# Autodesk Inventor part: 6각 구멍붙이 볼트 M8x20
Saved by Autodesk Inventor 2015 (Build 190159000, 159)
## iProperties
Created: 2025-06
Part Number: 6각 구멍붙이 볼트 M8x20
Material: 일반
Document SubType Name: Modeling
Designer: User
Density: 1 g/cm^3
Appearance: 기본값
Author: User
Author: jhkim
Description: 6각머리 태핑 나사
Creation Date: 2025-06-19
Sending System: Autodesk Inventor 2026
Preprocessor: ST-DEVELOPER v20.1
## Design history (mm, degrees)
node "6각 구멍붙이 볼트 M8x201"
body "Solid1"
node "기준1"
